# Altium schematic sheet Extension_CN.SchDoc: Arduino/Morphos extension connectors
size A4; Author: Ph.A; SheetNumber: 4; SheetTotal: 6
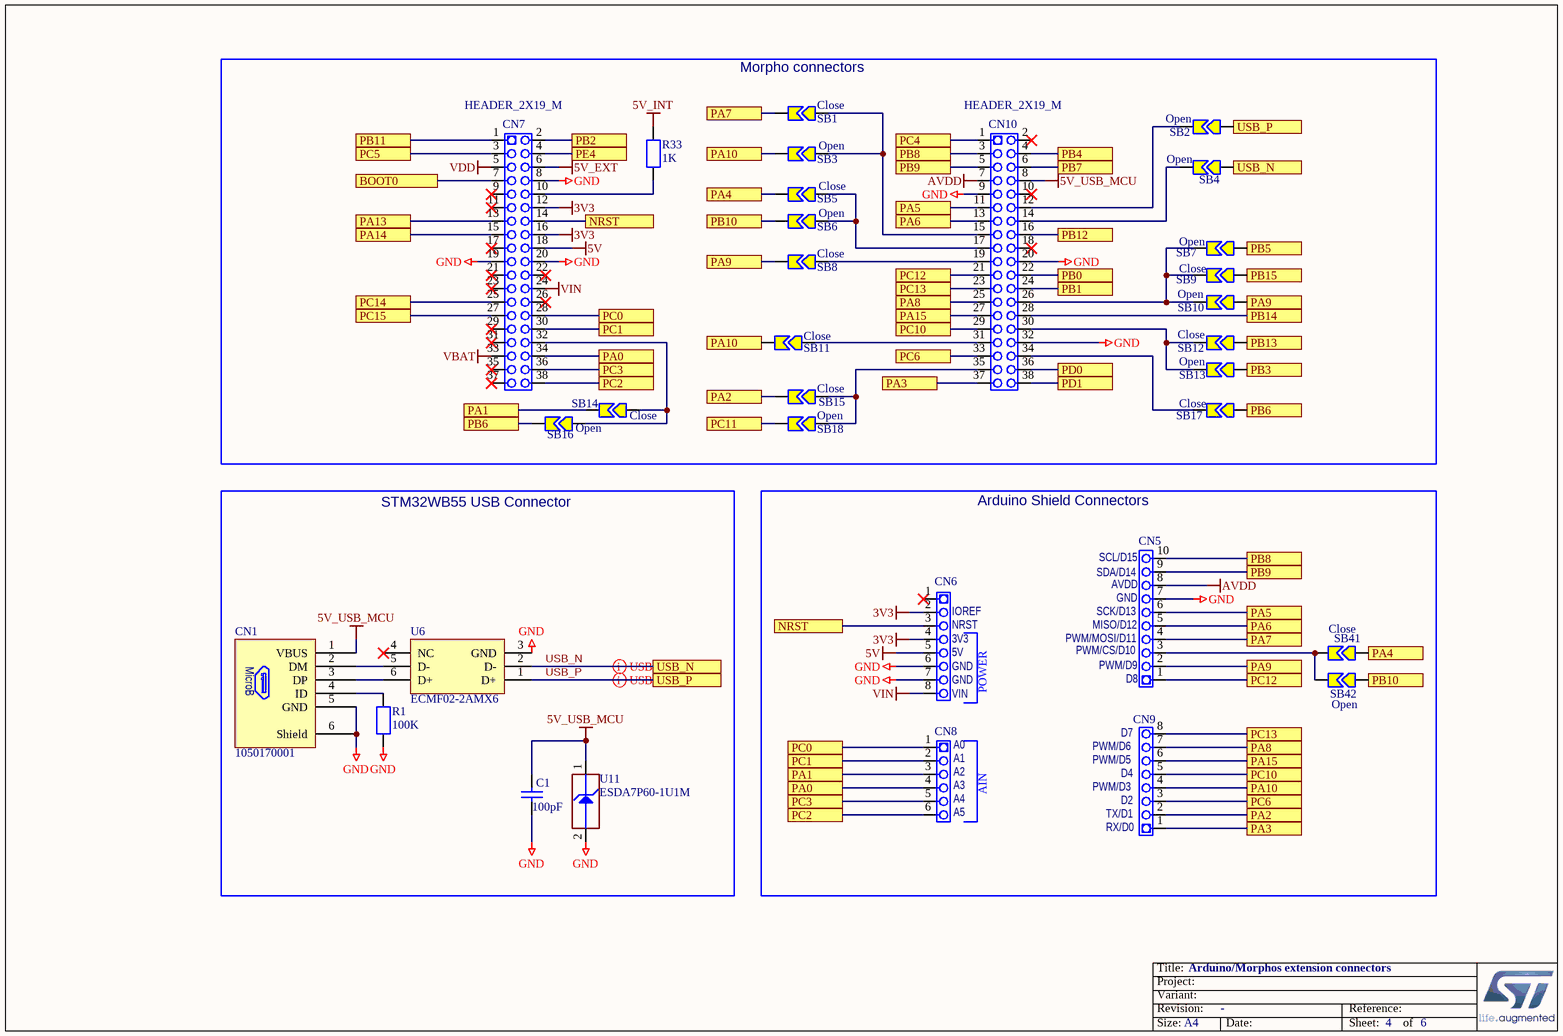
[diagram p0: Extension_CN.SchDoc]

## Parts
C1  value 100pF  [C0402]  (hidden comment: Capacitor)
CN1  1050170001  [USBMICROB_MOLEX_105017-0001_H2P90]
CN5  HEADER_1X10  [Header F 1x10x2.54 TH V]  (value not drawn)
CN6  HEADER_1X8_F  [Header F 1x8x2.54 TH V]  (value not drawn)
CN7  HEADER_2X19_M  [Header M 2x19x2.54 TH M_top + M_bottom]
CN8  HEADER_1X6  [Header F 1x6x2.54 TH V]  (value not drawn)
CN9  HEADER_1X8_F  [Header F 1x8x2.54 TH V]  (value not drawn)
CN10  HEADER_2X19_M  [Header M 2x19x2.54 TH M_top + M_bottom]
R1  100K  [0402_RES]
R33  1K  [0402_RES]
SB1  Close  [SB-tiny]
SB2  Open  [SB-tiny]
SB3  Open  [SB-tiny]
SB4  Open  [SB-tiny]
SB5  Close  [SB-tiny]
SB6  Open  [SB-tiny]
SB7  Open  [SB-tiny]
SB8  Close  [SB-tiny]
SB9  Close  [SB-tiny]
SB10  Open  [SB-tiny]
SB11  Close  [SB-tiny]
SB12  Close  [SB-tiny]
SB13  Open  [SB-tiny]
SB14  Close  [SB-tiny]
SB15  Close  [SB-tiny]
SB16  Open  [SB-tiny]
SB17  Close  [SB-tiny]
SB18  Open  [SB-tiny]
SB41  Close  [SB-tiny]
SB42  Open  [SB-tiny]
U6  ECMF02-2AMX6  [ESD_QFN-6L_1P7X1P5_P050]
U11  value ESDA7P60-1U1M  [ESD_QFN2_1P6X1_P125]  (hidden comment: ESD-TRANSIL)

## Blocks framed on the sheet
Morpho connectors: CN7 CN10 R33 SB1-SB18
STM32WB55 USB Connector: C1 CN1 R1 U6 U11
Arduino Shield Connectors: CN5 CN6 CN8 CN9 SB41 SB42

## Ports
BOOT0, NRST, PA0, PA1, PA2, PA3, PA4, PA5, PA6, PA7, PA8, PA9, PA10, PA13, PA14, PA15, PB0, PB1, PB2, PB3, PB4, PB5, PB6, PB7, PB8, PB9, PB10, PB11, PB12, PB13, PB14, PB15, PC0, PC1, PC2, PC3, PC4, PC5, PC6, PC10, PC11, PC12, PC13, PC14, PC15, PD0, PD1, PE4, USB_N, USB_P

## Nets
3V3: CN6.2 CN6.4 CN7.12 CN7.16
5V: CN6.5 CN7.18
5V_EXT: CN7.6
5V_INT: R33.2
5V_USB_MCU: C1.2 CN1.1(VBUS) CN10.8 U11.1(IO1)
AVDD: CN5.8 CN10.7
GND: C1.1 CN1.5(GND) CN1.6(Shield) CN5.7 CN6.6 CN6.7 CN7.8 CN7.19 CN7.20 CN10.9 CN10.20 CN10.32 R1.1 U6.3(GND) U11.2(GND)
VBAT: CN7.33
VDD: CN7.5
VIN: CN6.8 CN7.24
BOOT0: CN7.7 ; port BOOT0
NRST: CN6.3 CN7.14 ; port NRST
PA0: CN7.34 CN8.4 ; port PA0
PA1: CN8.3 SB14.2 ; port PA1
PA2: CN9.2 SB15.2 ; port PA2
PA3: CN9.1 CN10.37 ; port PA3
PA4: SB5.2 SB41.1 ; port PA4
PA5: CN5.6 CN10.11 ; port PA5
PA6: CN5.5 CN10.13 ; port PA6
PA7: CN5.4 SB1.2 ; port PA7
PA8: CN9.7 CN10.25 ; port PA8
PA9: CN5.2 SB8.2 SB10.1 ; port PA9
PA10: CN9.4 SB3.2 SB11.2 ; port PA10
PA13: CN7.13 ; port PA13
PA14: CN7.15 ; port PA14
PA15: CN9.6 CN10.27 ; port PA15
PB0: CN10.22 ; port PB0
PB1: CN10.24 ; port PB1
PB2: CN7.2 ; port PB2
PB3: SB13.1 ; port PB3
PB4: CN10.4 ; port PB4
PB5: SB7.1 ; port PB5
PB6: SB16.2 SB17.1 ; port PB6
PB7: CN10.6 ; port PB7
PB8: CN5.10 CN10.3 ; port PB8
PB9: CN5.9 CN10.5 ; port PB9
PB10: SB6.2 SB42.1 ; port PB10
PB11: CN7.1 ; port PB11
PB12: CN10.16 ; port PB12
PB13: SB12.1 ; port PB13
PB14: CN10.28 ; port PB14
PB15: SB9.1 ; port PB15
PC0: CN7.28 CN8.1 ; port PC0
PC1: CN7.30 CN8.2 ; port PC1
PC2: CN7.38 CN8.6 ; port PC2
PC3: CN7.36 CN8.5 ; port PC3
PC4: CN10.1 ; port PC4
PC5: CN7.3 ; port PC5
PC6: CN9.3 CN10.33 ; port PC6
PC10: CN9.5 CN10.29 ; port PC10
PC11: SB18.2 ; port PC11
PC12: CN5.1 CN10.21 ; port PC12
PC13: CN9.8 CN10.23 ; port PC13
PC14: CN7.25 ; port PC14
PC15: CN7.27 ; port PC15
PD0: CN10.36 ; port PD0
PD1: CN10.38 ; port PD1
PE4: CN7.4 ; port PE4
USB_N: SB4.1 U6.2(D-) ; port USB_N
USB_P: SB2.1 U6.1(D+) ; port USB_P
NetCN1_2: CN1.2(DM) U6.5(D-)
NetCN1_3: CN1.3(DP) U6.6(D+)
NetCN1_4: CN1.4(ID) R1.2
NetCN5_3: CN5.3 SB41.2 SB42.2
NetCN7_10: CN7.10 R33.1
NetCN7_32: CN7.32 SB14.1 SB16.1
NetCN10_12: CN10.12 SB2.2
NetCN10_14: CN10.14 SB4.2
NetCN10_15: CN10.15 SB1.1 SB3.1
NetCN10_17: CN10.17 SB5.1 SB6.1
NetCN10_19: CN10.19 SB8.1
NetCN10_26: CN10.26 SB7.2 SB9.2 SB10.2
NetCN10_30: CN10.30 SB12.2 SB13.2
NetCN10_31: CN10.31 SB11.1
NetCN10_34: CN10.34 SB17.2
NetCN10_35: CN10.35 SB15.1 SB18.1

Not connected (* = marked no-connect by the designer): CN6 1*; CN7 9* 11* 17* 21* 22* 23* 26* 29* 31* 35* 37*; CN10 2* 10* 18*; U6 4(NC)*

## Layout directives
differential pair; net class DIFF90: USB_N, USB_P

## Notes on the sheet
- (near CN5) SDA/D14
- (near CN5) SCL/D15
- (near CN6) 3V3
- (near CN6) NRST
- (near CN6) IOREF
- (near CN5) PWM/MOSI/D11
- (near CN5) PWM/CS/D10
- (near CN5) MISO/D12
- (near CN5) SCK/D13
- (near CN5) AVDD
- (near CN5) GND
- (near CN6) GND
- (near CN6) VIN
- (near CN6) 5V
- (near CN6) POWER
- (near CN5) PWM/D9
- (near CN5) D8
- (near CN8) A0
- (near CN8) A1
- (near CN8) A2
- (near CN8) A3
- (near CN8) AIN
- (near CN9) PWM/D3
- (near CN9) PWM/D5
- (near CN9) PWM/D6
- (near CN9) D4
- (near CN9) D7
- (near CN8) A5
- (near CN8) A4
- (near CN9) RX/D0
- (near CN9) TX/D1
- (near CN9) D2

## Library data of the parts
C1 = MCD-00205: Capacitor, MLCC, 100pF, 50V, NPO, 5%, 0402, T=0,5mm; Manufacturer_Part_Number: CC0402JRNPO9BN101; Manufacturer: YAGEO; ECCN_US: EAR99; ECCN_EU: NEC; Provided_By: SUBCO
CN1 = 1050170001: USB-MICRO-B, 1050170001, SMT, MOLEX; Fitted: YES; Ordered_By: Subcon
CN6 = HEADER_1X8: Specific Function: Arduino Power
CN7 = HEADER_2X19: Specific Function: Morpho CN7
CN9 = HEADER_1X8: Specific Function: Arduino Digital 1
CN10 = HEADER_2X19: Specific Function: Morpho CN10
R1 R33 = RES: Resistor
SB1-SB18 SB41 SB42 = Strap2: Solder Jumper; Solder: YES
U6 = MCD-00649: Common mode filter with ESD protection for USB 2.0 interface; Part_Type: Diode; Manufacturer: STMICROELECTRONICS; BMS_Part_Number: 9151138; ECCN_US: EAR99; ECCN_EU: NEC; Provided_By: SUBCO with ST control
U11 = MCD-00251: High power transient voltage suppressor, 7V breakdown; Part_Type: Diode; Manufacturer: STMICROELECTRONICS; BMS_Part_Number: 9179042; ECCN_US: EAR99; ECCN_EU: NEC; Provided_By: SUBCO with ST control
